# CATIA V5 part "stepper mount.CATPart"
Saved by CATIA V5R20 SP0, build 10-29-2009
Part number: stepper mount
Source: Unknown
Bounding box of the stored display mesh (mm): x 0 to 45, y 0 to 48.3, z -50 to 42.3
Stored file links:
  C:\Users\Ikarus\OneDrive - FH JOANNEUM\BAC - Arbeit 1\CAD Modell\CAD-Modell-Step files\stepper mount\stepper mount.CATPart
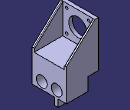
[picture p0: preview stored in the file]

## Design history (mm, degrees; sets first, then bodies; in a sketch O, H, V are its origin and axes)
Body1 (main body)
  Solid1 "Hauptkörper": solid without history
